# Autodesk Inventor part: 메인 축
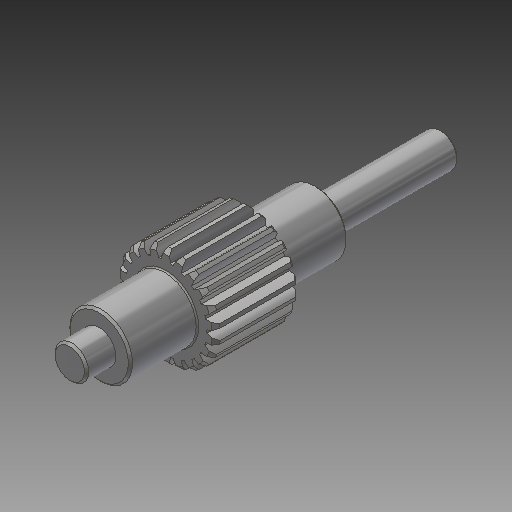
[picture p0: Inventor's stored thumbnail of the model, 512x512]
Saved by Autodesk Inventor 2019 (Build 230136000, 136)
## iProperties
Created: 2016-02
Part Number: 메인 축
Material: 강철, 연강
Document SubType Name: Modeling
Categories: <?xml version="1.0" encoding="UTF-16"?> <MemberInstance><Categories><FamilyTemplate><FamilyTemplateParameter ValueType="xs:double" Id="1" ObjectReferenceKey="da
Density: 7.86 g/cm^3
Appearance: 강철
CustomPartVersion: 1
Author: mdu
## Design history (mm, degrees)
sketch "Sketch1"
  geometry: C1 r 12 at (0, 0)
  constraints: 1 centre point
  dimensions: "d0" = 24 diameter of C1 (= da_da)
extrude "Extrusion1" new body sketch "Sketch1" distance "d1" = 20 (= da_b); taper "d2" = 0 deg
workplane "Work Plane2"
feature "피치 지름" dims "d4" = 10, "d5" = 0
workplane "Work Plane8"
workplane "Work Plane9"
chamfer "모따기1" distance "d49" = 1; stored, may be unused: second distance "d50" = 2, angle "d51" = 45 deg
sketch "스케치3"
  geometry: C1 r 7.5 at (0, 0); 1 further point
  constraints: 1 centre point, 1 coincident
  dimensions: "d52" = 15 diameter of C1
extrude "돌출2" join sketch "스케치3" distance "d53" = 16; taper "d54" = 0 deg
sketch "스케치4"
  geometry: C1 r 4 at (0, 0); 1 further point
  constraints: 1 centre point, 1 coincident
  dimensions: "d55" = 8 diameter of C1
extrude "돌출3" join sketch "스케치4" distance "d56" = 7; taper "d57" = 0 deg
sketch "스케치5"
  geometry: C1 r 7.5 at (0, 0) reference; C2 r 7.5 at (0, 0) reference; 1 further point
extrude "돌출4" join sketch "스케치5" distance "d62" = 16; taper "d63" = 0 deg
sketch "스케치6"
  geometry: C1 r 4 at (0, 0); 1 further point
  constraints: 1 centre point, 1 coincident
  dimensions: "d64" = 8 diameter of C1
extrude "돌출5" join sketch "스케치6" distance "d65" = 30; taper "d66" = 0 deg
chamfer "모따기2" distance "d58" = 0.5; stored, may be unused: second distance "d59" = 2, angle "d60" = 45 deg
fillet "모깎기1" dims "d61" = 0.3
feature "스퍼 기어" dims "da_b" = 20, "da_d" = 22, "da_aw" = 31, "da_da" = 24, "da_df" = 19.5, "da_dw" = 22, angle "da_beta" = 0 deg, "da_lefttooth" = 0, "da_righttooth" = 0
body "Solid1"
sketch "Sketch2"
  geometry: C1 r 12 at (0, 0) reference; C2 r 11 at (0, 0)
  constraints: 1 centre point, 1 coincident
  dimensions: "d3" = 22 diameter of C2 (= da_dw)
body "Srf1"
node "투영된 루프1"
other parameters: "d16" = 31 (= da_aw), "d17" = 0, "d34" = 1.428 (computed from da_z), "d39" = 0, "d41" = 0, "d43" = 31 (= da_aw), "d46" = 31 (= da_aw), "d47" = 0, "d48" = 0
